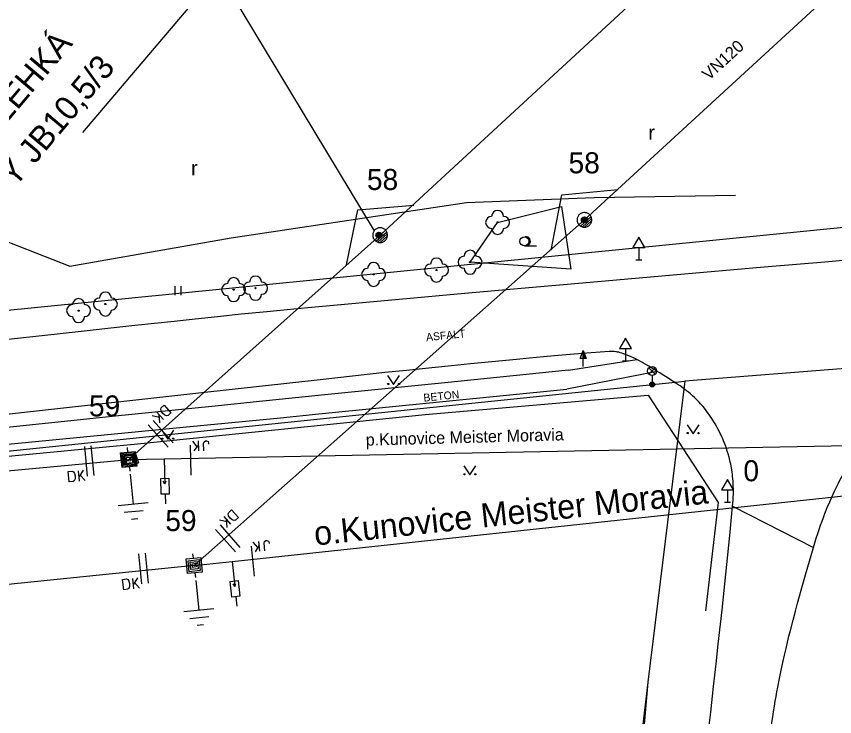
# Model space of a CAD drawing. Extents: x -540150 to -533593, y -1185082 to -1180066.
# Drawn here: x -536508.6 to -536440.4, y -1183065 to -1183006.7 of the extents above; entities that cross this region are included whole.
import ezdxf

# ---------------------------------------------------------------- set-up
doc = ezdxf.new("R2010")
doc.units = 0
for name, color, linetype in [('KN_HRAN_PARCEL', 7, 'Continuous'), ('KN_VKP_HRAN_', 7, 'Continuous'), ('popis demontáže', 7, 'Continuous'), ('Vrstva 1', 7, 'Continuous'), ('Vrstva 10', 7, 'Continuous'), ('Vrstva 11', 7, 'Continuous'), ('Vrstva 12', 7, 'Continuous'), ('Vrstva 13', 7, 'Continuous'), ('Vrstva 14', 7, 'Continuous'), ('Vrstva 15', 7, 'Continuous'), ('Vrstva 16', 7, 'Continuous'), ('Vrstva 18', 7, 'Continuous'), ('Vrstva 2', 7, 'Continuous'), ('Vrstva 21', 7, 'Continuous'), ('Vrstva 22', 7, 'Continuous'), ('Vrstva 23', 7, 'Continuous'), ('Vrstva 25', 7, 'Continuous'), ('Vrstva 3', 7, 'Continuous'), ('Vrstva 33', 7, 'Continuous'), ('Vrstva 34', 7, 'Continuous'), ('Vrstva 36', 7, 'Continuous'), ('Vrstva 4', 7, 'Continuous'), ('Vrstva 40', 7, 'Continuous'), ('Vrstva 52', 7, 'Continuous'), ('Vrstva 54', 7, 'Continuous'), ('Vrstva 59', 7, 'Continuous'), ('Vrstva 7', 7, 'Continuous')]:
    doc.layers.add(name, color=color, linetype=linetype)

# ---------------------------------------------------------------- blocks, each defined once
blk = doc.blocks.new('VN440')
at = {"layer": 'Vrstva 2'}
for points in [[(1.22, 0), (1.21, 0.13), (1.19, 0.25), (1.16, 0.38), (1.11, 0.5), (1.05, 0.61), (0.98, 0.72), (0.9, 0.82), (0.81, 0.91), (0.71, 0.99), (0.6, 1.06), (0.49, 1.12), (0.37, 1.16), (0.25, 1.2), (0.12, 1.22), (-0.01, 1.22), (-0.14, 1.22), (-0.26, 1.2), (-0.39, 1.16), (-0.51, 1.12), (-0.62, 1.06), (-0.73, 0.99), (-0.83, 0.91), (-0.92, 0.82), (-1, 0.72), (-1.07, 0.61), (-1.13, 0.5), (-1.18, 0.38), (-1.21, 0.25), (-1.23, 0.13), (-1.24, 0), (-1.23, -0.13), (-1.21, -0.26), (-1.18, -0.38), (-1.13, -0.5), (-1.07, -0.62), (-1, -0.73), (-0.92, -0.83), (-0.83, -0.92), (-0.73, -1), (-0.62, -1.07), (-0.51, -1.13), (-0.39, -1.17), (-0.26, -1.2), (-0.14, -1.23), (-0.01, -1.23), (0.12, -1.23), (0.25, -1.2), (0.37, -1.17), (0.49, -1.13), (0.6, -1.07), (0.71, -1), (0.81, -0.92), (0.9, -0.83), (0.98, -0.73), (1.05, -0.62), (1.11, -0.5), (1.16, -0.38), (1.19, -0.26), (1.21, -0.13), (1.22, 0)], [(-1.24, 0), (1.22, 0)], [(-1.18, -0.34), (1.1, -0.34)], [(-1.01, -0.63), (0.97, -0.63)], [(-0.74, -0.92), (0.68, -0.92)]]:
    blk.add_lwpolyline(points, dxfattribs=at)
blk = doc.blocks.new('VN850')
at = {"layer": 'Vrstva 15'}
for points in [[(-0.565, 1.426), (-0.565, -1.074)], [(-0.014, 1.426), (-0.014, -1.074)], [(-2.091, -0.542), (-1.776, -0.542)], [(-2.091, -1.409), (-2.091, -0.542)], [(-1.776, -0.542), (-1.657, -0.602)], [(-1.657, -0.602), (-1.588, -0.749)], [(-1.264, -0.542), (-1.264, -1.409)], [(-0.85, -0.542), (-1.264, -1.094)], [(-1.667, -1.35), (-1.776, -1.409)], [(-1.588, -1.202), (-1.667, -1.35)], [(-1.588, -0.749), (-1.549, -0.956)], [(-1.549, -0.956), (-1.588, -1.202)], [(-1.126, -0.917), (-0.772, -1.409)], [(-1.776, -1.409), (-2.091, -1.409)]]:
    blk.add_lwpolyline(points, dxfattribs=at)
blk = doc.blocks.new('VN840')
at = {"layer": 'Vrstva 15'}
for points in [[(-0.009, 1.414), (-0.009, -1.086)], [(-1.092, -0.594), (-1.092, -1.243)], [(-0.678, -0.594), (-0.678, -1.421)], [(-0.678, -1.106), (-0.265, -0.594)], [(-1.505, -1.243), (-1.505, -1.145)], [(-1.476, -1.352), (-1.505, -1.243)], [(-1.328, -1.421), (-1.476, -1.352)], [(-1.131, -1.352), (-1.269, -1.421)], [(-1.092, -1.243), (-1.131, -1.352)], [(-0.541, -0.938), (-0.196, -1.421)], [(-1.269, -1.421), (-1.328, -1.421)]]:
    blk.add_lwpolyline(points, dxfattribs=at)
blk = doc.blocks.new('VN860')
at = {"layer": 'Vrstva 15'}
for points in [[(-3.738, 0.001), (0.012, 2.82)], [(0.012, 2.82), (3.762, 0.001)]]:
    blk.add_lwpolyline(points, dxfattribs=at)
blk = doc.blocks.new('VN820')
at = {"layer": 'Vrstva 13'}
for points in [[(0.003, 0.002), (0.003, -2.105)], [(-0.322, -1.632), (0.338, -1.632)], [(-0.322, -2.951), (-0.322, -1.632)], [(0.003, -2.105), (-0.115, -1.859)], [(0.003, -2.105), (0.121, -1.859)], [(0.338, -1.632), (0.338, -2.951)], [(0.338, -2.951), (-0.322, -2.951)], [(0.003, -2.951), (0.003, -3.748)]]:
    blk.add_lwpolyline(points, dxfattribs=at)
blk = doc.blocks.new('VN810')
at = {"layer": 'Vrstva 14'}
for points in [[(0.004, -1.247), (0.004, -3.747)], [(1.254, -3.747), (-1.246, -3.747)], [(0.772, -4.367), (-0.803, -4.367)], [(0.004, -4.997), (-0.252, -4.997)], [(0.27, -4.997), (0.004, -4.997)]]:
    blk.add_lwpolyline(points, dxfattribs=at)
blk = doc.blocks.new('VN470')
at = {"layer": 'Vrstva 2'}
for points in [[(0, 1.22), (0, 1.97)], [(-1.23, 1.22), (1.23, 1.22)], [(-1.23, -1.23), (-1.23, 1.22)], [(-0.92, 0.9), (0.92, 0.9)], [(-0.92, -0.95), (-0.92, 0.9)], [(-0.61, 0.61), (0.61, 0.61)], [(-0.61, -0.62), (-0.61, 0.61)], [(-0.31, -0.27), (-0.31, 0.34)], [(-0.31, 0.34), (0.31, 0.34)], [(0.31, 0.34), (0.31, -0.27)], [(0.61, 0.61), (0.61, -0.62)], [(0.92, 0.9), (0.92, -0.95)], [(1.23, 1.22), (1.23, -1.23)], [(1.23, -1.23), (-1.23, -1.23)], [(0.92, -0.95), (-0.92, -0.95)], [(0.61, -0.62), (-0.61, -0.62)], [(0.31, -0.27), (-0.31, -0.27)], [(0, -1.23), (0, -1.98)]]:
    blk.add_lwpolyline(points, dxfattribs=at)

msp = doc.modelspace()

# ---------------------------------------------------------------- linework, layer by layer
at = {"layer": 'KN_HRAN_PARCEL'}
for p, q in [((-536420.27, -1183022.305), (-536523.7, -1183032.575)), ((-536401.06, -1183033.005), (-536452.92, -1183037.025)), ((-536549.916, -1183047.069), (-536452.92, -1183037.025)), ((-536452.92, -1183037.025), (-536456, -1183062.095)), ((-536456, -1183062.095), (-536459.39, -1183089.795))]:
    msp.add_line(p, q, dxfattribs=at)
at = {"layer": 'KN_VKP_HRAN_'}
msp.add_line((-536456, -1183062.095), (-536464.67, -1183156.935), dxfattribs=at)
at = {"layer": 'popis demontáže'}
msp.add_lwpolyline([(-536503.077, -1183016.334), (-536491.77, -1183003.019), (-536478.809, -1183024.516)], dxfattribs=at)
at = {"layer": 'Vrstva 1'}
for points in [[(-535333.019, -1181707.832), (-535332.528, -1181735.448), (-535362.49, -1181817.717), (-535394.17, -1181900.488), (-535426.424, -1181985.389), (-535455.768, -1182060.901), (-535484.739, -1182136.414), (-535558.599, -1182202.844), (-535640.844, -1182277.719), (-535712.992, -1182341.229), (-535787.765, -1182409.749), (-535866.419, -1182480.663), (-535946.042, -1182552.999), (-536025.292, -1182625.409), (-536105.737, -1182698.417), (-536184.987, -1182770.529), (-536271.131, -1182848.999), (-536335.755, -1182908.243), (-536401.721, -1182968.908), (-536461.289, -1183023.605), (-536493.807, -1183052.389)], [(-536499.259, -1183043.554), (-536478.31, -1183024.875), (-536408.53, -1182960.475), (-536346.218, -1182903.25), (-536276.596, -1182839.443), (-536191.423, -1182762.095), (-536111.799, -1182689.909), (-536032.399, -1182617.798), (-535952.252, -1182544.864), (-535872.16, -1182472.665)], [(-536551.039, -1183048.391), (-536499.259, -1183043.554)], [(-536493.807, -1183052.389), (-536560.174, -1183059.148)]]:
    msp.add_lwpolyline(points, dxfattribs=at)
at = {"layer": 'Vrstva 10'}
for p, q in [((-536441.274, -1183027.117), (-536446.321, -1183027.554)), ((-536438.391, -1183026.866), (-536441.274, -1183027.117)), ((-536446.321, -1183027.554), (-536453.891, -1183028.205)), ((-536461.46, -1183028.865), (-536466.876, -1183029.346)), ((-536470.937, -1183029.709), (-536477.029, -1183030.259)), ((-536466.876, -1183029.346), (-536470.937, -1183029.709)), ((-536477.029, -1183030.259), (-536483.12, -1183030.815)), ((-536498.745, -1183032.416), (-536504.472, -1183033.048)), ((-536472.36, -1183035.751), (-536473.73, -1183035.891)), ((-536483.31, -1183036.915), (-536493.16, -1183038.001)), ((-536493.16, -1183038.001), (-536507.935, -1183039.637)), ((-536507.935, -1183039.637), (-536515.322, -1183040.453)), ((-536499.893, -1183043.066), (-536498.771, -1183042.922)), ((-536499.749, -1183044.188), (-536499.893, -1183043.066)), ((-536499.669, -1183043.239), (-536498.944, -1183043.146)), ((-536499.576, -1183043.964), (-536499.669, -1183043.239)), ((-536498.944, -1183043.146), (-536498.851, -1183043.871)), ((-536498.771, -1183042.922), (-536498.627, -1183044.044)), ((-536498.627, -1183044.044), (-536499.749, -1183044.188)), ((-536498.851, -1183043.871), (-536499.576, -1183043.964)), ((-536449.599, -1183053.915), (-536449.431, -1183052.299)), ((-536450.772, -1183064.605), (-536450.527, -1183062.46))]:
    msp.add_line(p, q, dxfattribs=at)
for points in [[(-536453.891, -1183028.205), (-536457.676, -1183028.533), (-536461.46, -1183028.865)], [(-536483.12, -1183030.815), (-536484.326, -1183030.927), (-536485.494, -1183031.038), (-536487.756, -1183031.259), (-536489.876, -1183031.472), (-536491.863, -1183031.678)], [(-536491.863, -1183031.678), (-536493.726, -1183031.874), (-536495.472, -1183032.061), (-536498.745, -1183032.416)], [(-536504.472, -1183033.048), (-536508.767, -1183033.522), (-536511.989, -1183033.872), (-536514.406, -1183034.13)], [(-536454.801, -1183036.49), (-536455.01, -1183036.358), (-536455.22, -1183036.225), (-536455.43, -1183036.091), (-536455.612, -1183035.976), (-536455.931, -1183035.78), (-536456.173, -1183035.638), (-536456.357, -1183035.533), (-536456.497, -1183035.457), (-536456.71, -1183035.344), (-536456.93, -1183035.235), (-536457.21, -1183035.101), (-536457.456, -1183034.986), (-536457.673, -1183034.891), (-536457.863, -1183034.814), (-536458.031, -1183034.753), (-536458.179, -1183034.704), (-536458.308, -1183034.666), (-536458.422, -1183034.637), (-536458.522, -1183034.615), (-536458.609, -1183034.599), (-536458.686, -1183034.586), (-536458.821, -1183034.57), (-536458.923, -1183034.562), (-536458.999, -1183034.559), (-536459.115, -1183034.559), (-536459.23, -1183034.565), (-536460.734, -1183034.684), (-536462.145, -1183034.8), (-536463.468, -1183034.912)], [(-536463.468, -1183034.912), (-536464.708, -1183035.021), (-536465.871, -1183035.126), (-536466.962, -1183035.226), (-536469.006, -1183035.42), (-536470.795, -1183035.595), (-536472.36, -1183035.751)], [(-536473.73, -1183035.891), (-536476.126, -1183036.14), (-536477.923, -1183036.33), (-536480.617, -1183036.621), (-536483.31, -1183036.915)], [(-536449.074, -1183044.104), (-536449.104, -1183043.948), (-536449.136, -1183043.796), (-536449.17, -1183043.65), (-536449.24, -1183043.367), (-536449.313, -1183043.102), (-536449.388, -1183042.855), (-536449.464, -1183042.625), (-536449.54, -1183042.409), (-536449.616, -1183042.208), (-536449.691, -1183042.02), (-536449.765, -1183041.844), (-536449.837, -1183041.68), (-536449.908, -1183041.527), (-536449.977, -1183041.383), (-536450.043, -1183041.249), (-536450.174, -1183040.999), (-536450.294, -1183040.782), (-536450.404, -1183040.592), (-536450.504, -1183040.427), (-536450.594, -1183040.284), (-536450.675, -1183040.158), (-536450.822, -1183039.94), (-536450.936, -1183039.778), (-536451.024, -1183039.656), (-536451.16, -1183039.475), (-536451.3, -1183039.295), (-536451.41, -1183039.16), (-536451.517, -1183039.032), (-536451.622, -1183038.913), (-536451.725, -1183038.801), (-536451.825, -1183038.695), (-536451.922, -1183038.595), (-536452.017, -1183038.501), (-536452.11, -1183038.412), (-536452.291, -1183038.246), (-536452.463, -1183038.096), (-536452.625, -1183037.961), (-536452.779, -1183037.838), (-536452.925, -1183037.727), (-536453.062, -1183037.625), (-536453.322, -1183037.44), (-536453.552, -1183037.283), (-536453.755, -1183037.149), (-536454.114, -1183036.918), (-536454.387, -1183036.747), (-536454.801, -1183036.49)], [(-536449.431, -1183052.299), (-536449.183, -1183049.877), (-536448.94, -1183047.455), (-536448.916, -1183047.191), (-536448.899, -1183046.936), (-536448.887, -1183046.688), (-536448.88, -1183046.449), (-536448.878, -1183046.216), (-536448.88, -1183045.991), (-536448.886, -1183045.774), (-536448.896, -1183045.563), (-536448.91, -1183045.359), (-536448.926, -1183045.161), (-536448.945, -1183044.97), (-536448.967, -1183044.785), (-536448.991, -1183044.607), (-536449.016, -1183044.434), (-536449.044, -1183044.266), (-536449.074, -1183044.104)], [(-536441.852, -1183049.733), (-536441.733, -1183049.376), (-536441.614, -1183049.031), (-536441.496, -1183048.7), (-536441.378, -1183048.38), (-536441.261, -1183048.071), (-536441.144, -1183047.774), (-536441.028, -1183047.487), (-536440.913, -1183047.211), (-536440.798, -1183046.945), (-536440.685, -1183046.689), (-536440.572, -1183046.441), (-536440.46, -1183046.203), (-536440.35, -1183045.973), (-536440.241, -1183045.752), (-536440.132, -1183045.539), (-536440.026, -1183045.333), (-536439.92, -1183045.135), (-536439.816, -1183044.944), (-536439.713, -1183044.76), (-536439.509, -1183044.405), (-536439.311, -1183044.076), (-536439.119, -1183043.771)], [(-536442.09, -1183050.487), (-536441.971, -1183050.103), (-536441.852, -1183049.733)], [(-536444.624, -1183059.857), (-536444.494, -1183059.294), (-536444.369, -1183058.767), (-536444.248, -1183058.273), (-536444.134, -1183057.81), (-536443.912, -1183056.944), (-536443.713, -1183056.186), (-536443.535, -1183055.524), (-536443.376, -1183054.944), (-536443.093, -1183053.93), (-536442.876, -1183053.169), (-536442.546, -1183052.028), (-536442.21, -1183050.885), (-536442.09, -1183050.487)], [(-536450.527, -1183062.46), (-536450.317, -1183060.584), (-536450.136, -1183058.942), (-536449.826, -1183056.069), (-536449.599, -1183053.915)], [(-536445.181, -1183062.518), (-536445.038, -1183061.785), (-536444.896, -1183061.099), (-536444.758, -1183060.458), (-536444.624, -1183059.857)], [(-536446.471, -1183071.943), (-536446.139, -1183069.184), (-536445.8, -1183066.425), (-536445.736, -1183065.931), (-536445.671, -1183065.453), (-536445.603, -1183064.991), (-536445.534, -1183064.544), (-536445.465, -1183064.111), (-536445.394, -1183063.693), (-536445.323, -1183063.288), (-536445.252, -1183062.897), (-536445.181, -1183062.518)], [(-536451.763, -1183072.826), (-536451.565, -1183071.241), (-536451.383, -1183069.755), (-536451.214, -1183068.362), (-536451.059, -1183067.055), (-536450.772, -1183064.605)]]:
    msp.add_lwpolyline(points, dxfattribs=at)
at = {"layer": 'Vrstva 11'}
for p, q in [((-536462.63, -1183036.125), (-536456.93, -1183035.235)), ((-536462.63, -1183036.125), (-536472.91, -1183037.165)), ((-536455.22, -1183036.225), (-536462.76, -1183037.705)), ((-536472.91, -1183037.165), (-536483.19, -1183038.205)), ((-536473.095, -1183038.735), (-536462.76, -1183037.705)), ((-536483.43, -1183039.765), (-536473.095, -1183038.735)), ((-536492.346, -1183039.139), (-536499.822, -1183039.91)), ((-536499.822, -1183039.91), (-536511.036, -1183041.074)), ((-536496.179, -1183041.017), (-536489.804, -1183040.395)), ((-536517.432, -1183043.065), (-536500.43, -1183041.428)), ((-536500.43, -1183041.428), (-536496.179, -1183041.017)), ((-536448.94, -1183047.455), (-536442.21, -1183050.885))]:
    msp.add_line(p, q, dxfattribs=at)
for points in [[(-536483.19, -1183038.205), (-536488.073, -1183038.701), (-536492.346, -1183039.139)], [(-536489.804, -1183040.395), (-536486.617, -1183040.081), (-536483.43, -1183039.765)]]:
    msp.add_lwpolyline(points, dxfattribs=at)
at = {"layer": 'Vrstva 21'}
msp.add_lwpolyline([(-536468.52, -1183023.815), (-536463.19, -1183022.495), (-536462.41, -1183027.715), (-536470.82, -1183027.135), (-536468.52, -1183023.815)], dxfattribs=at)
at = {"layer": 'Vrstva 22'}
for centre in [(-536468.52, -1183023.815), (-536470.82, -1183027.135), (-536473.61, -1183027.785), (-536478.85, -1183028.145), (-536490.52, -1183029.415), (-536488.69, -1183029.295), (-536501.2, -1183030.615), (-536503.43, -1183031.165)]:
    msp.add_circle(centre, 0.05, dxfattribs=at)
for centre, start, end in [((-536468.52, -1183023.315), 0, 180), ((-536469.02, -1183023.815), 90, 270), ((-536468.02, -1183023.815), 270, 90), ((-536468.52, -1183024.315), 180, 0), ((-536470.82, -1183026.635), 0, 180), ((-536478.85, -1183027.645), 0, 180), ((-536473.61, -1183027.285), 0, 180), ((-536471.32, -1183027.135), 90, 270), ((-536470.32, -1183027.135), 270, 90), ((-536479.35, -1183028.145), 90, 270), ((-536478.35, -1183028.145), 270, 90), ((-536474.11, -1183027.785), 90, 270), ((-536473.11, -1183027.785), 270, 90), ((-536470.82, -1183027.635), 180, 0), ((-536490.52, -1183028.915), 0, 180), ((-536488.69, -1183028.795), 0, 180), ((-536473.61, -1183028.285), 180, 0), ((-536491.02, -1183029.415), 90, 270), ((-536490.02, -1183029.415), 270, 90), ((-536489.19, -1183029.295), 90, 270), ((-536488.19, -1183029.295), 270, 90), ((-536478.85, -1183028.645), 180, 0), ((-536501.2, -1183030.115), 0, 180), ((-536490.52, -1183029.915), 180, 0), ((-536488.69, -1183029.795), 180, 0), ((-536503.43, -1183030.665), 0, 180), ((-536501.7, -1183030.615), 90, 270), ((-536500.7, -1183030.615), 270, 90), ((-536503.93, -1183031.165), 90, 270), ((-536502.93, -1183031.165), 270, 90), ((-536501.2, -1183031.115), 180, 0), ((-536503.43, -1183031.665), 180, 0)]:
    msp.add_arc(centre, 0.5, start, end, dxfattribs=at)
at = {"layer": 'Vrstva 23'}
msp.add_lwpolyline([(-536520.38, -1183017.135), (-536515.51, -1183023.015), (-536504.15, -1183027.465), (-536490.71, -1183025.095), (-536471.12, -1183022.165), (-536460.47, -1183021.735), (-536448.71, -1183021.545)], dxfattribs=at)
at = {"layer": 'Vrstva 25'}
for p, q in [((-536461.642, -1183035.163), (-536461.39, -1183034.489)), ((-536461.39, -1183035.163), (-536461.642, -1183035.163)), ((-536461.39, -1183035.815), (-536461.39, -1183035.165))]:
    msp.add_line(p, q, dxfattribs=at)
for points in [[(-536461.14, -1183035.165), (-536461.39, -1183035.165), (-536461.39, -1183034.489), (-536461.39, -1183034.489)], [(-536461.197, -1183035.125), (-536461.35, -1183035.125), (-536461.35, -1183034.712)], [(-536461.255, -1183035.085), (-536461.31, -1183035.085), (-536461.31, -1183034.936)]]:
    msp.add_lwpolyline(points, close=True, dxfattribs=at)
for centre, radius in [((-536461.29, -1183023.605), 0.25), ((-536461.29, -1183023.605), 0.2), ((-536461.29, -1183023.605), 0.15), ((-536461.29, -1183023.605), 0.1), ((-536461.29, -1183023.605), 0.05), ((-536478.41, -1183024.885), 0.25), ((-536478.41, -1183024.885), 0.2), ((-536478.41, -1183024.885), 0.15), ((-536478.41, -1183024.885), 0.1), ((-536478.41, -1183024.885), 0.05)]:
    msp.add_circle(centre, radius, dxfattribs=at)
at = {"layer": 'Vrstva 33'}
for p, q in [((-536455.915, -1183036.455), (-536455.385, -1183035.925)), ((-536455.915, -1183035.925), (-536455.385, -1183036.455)), ((-536455.65, -1183036.565), (-536455.65, -1183037.315))]:
    msp.add_line(p, q, dxfattribs=at)
for centre, radius in [((-536455.65, -1183036.19), 0.375), ((-536455.65, -1183037.315), 0.2), ((-536455.65, -1183037.315), 0.145), ((-536455.65, -1183037.315), 0.0876)]:
    msp.add_circle(centre, radius, dxfattribs=at)
at = {"layer": 'Vrstva 34'}
for p, q in [((-536456.76, -1183025.917), (-536456.76, -1183026.935)), ((-536457.01, -1183026.935), (-536456.51, -1183026.935)), ((-536457.88, -1183034.317), (-536457.88, -1183035.335)), ((-536458.13, -1183035.335), (-536457.63, -1183035.335)), ((-536449.36, -1183046.097), (-536449.36, -1183047.115)), ((-536449.61, -1183047.115), (-536449.11, -1183047.115))]:
    msp.add_line(p, q, dxfattribs=at)
for points in [[(-536457.26, -1183025.917), (-536456.26, -1183025.917), (-536456.76, -1183025.051)], [(-536458.38, -1183034.317), (-536457.38, -1183034.317), (-536457.88, -1183033.451)], [(-536449.86, -1183046.097), (-536448.86, -1183046.097), (-536449.36, -1183045.231)]]:
    msp.add_lwpolyline(points, close=True, dxfattribs=at)
at = {"layer": 'Vrstva 36'}
for p, q in [((-536466.285, -1183025.776), (-536465.285, -1183025.776)), ((-536495.398, -1183029.871), (-536495.398, -1183029.121)), ((-536494.898, -1183029.871), (-536494.898, -1183029.121))]:
    msp.add_line(p, q, dxfattribs=at)
for points in [[(-536477.685, -1183036.573), (-536477.185, -1183037.323), (-536476.685, -1183036.573)], [(-536452.734, -1183040.661), (-536452.234, -1183041.411), (-536451.734, -1183040.661)], [(-536496.504, -1183041.124), (-536496.004, -1183041.874), (-536495.504, -1183041.124)], [(-536471.334, -1183044.092), (-536470.834, -1183044.842), (-536470.334, -1183044.092)]]:
    msp.add_lwpolyline(points, dxfattribs=at)
for centre, radius in [((-536466.285, -1183025.4), 0.375), ((-536477.635, -1183037.272), 0.05), ((-536476.735, -1183037.272), 0.05), ((-536452.685, -1183041.361), 0.05), ((-536451.785, -1183041.361), 0.05), ((-536496.454, -1183041.824), 0.05), ((-536495.555, -1183041.824), 0.05), ((-536471.284, -1183044.792), 0.05), ((-536470.385, -1183044.792), 0.05)]:
    msp.add_circle(centre, radius, dxfattribs=at)
msp.add_arc((-536466.16, -1183025.4), 0.375, 260.40593, 99.59407, dxfattribs=at)
at = {"layer": 'Vrstva 4'}
msp.add_lwpolyline([(-536499.259, -1183043.554), (-536496.312, -1183043.495), (-536432.17, -1183042.245)], dxfattribs=at)
at = {"layer": 'Vrstva 52'}
msp.add_lwpolyline([(-536493.807, -1183052.389), (-536490.644, -1183052.05), (-536434.5, -1183046.025)], dxfattribs=at)
at = {"layer": 'Vrstva 7'}
for p, q in [((-536522.12, -1183044.495), (-536498.52, -1183042.245)), ((-536499.329, -1183044.14), (-536498.449, -1183043.85))]:
    msp.add_line(p, q, dxfattribs=at)
for points in [[(-536498.52, -1183042.245), (-536474.56, -1183039.825), (-536455.97, -1183038.205), (-536450.15, -1183047.135), (-536451.2, -1183056.165)], [(-536499.329, -1183044.14), (-536499.61, -1183043.285), (-536498.73, -1183042.995), (-536498.449, -1183043.85)]]:
    msp.add_lwpolyline(points, dxfattribs=at)

# ---------------------------------------------------------------- block references
at = {"layer": 'Vrstva 13'}
for name, p, xscale, yscale, rotation in [('VN440', (-536461.289, -1183023.605), 0.5, 0.5, 41.44218061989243), ('VN440', (-536478.311, -1183024.875), 0.5, 0.5, 41.722772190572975), ('VN440', (-536478.311, -1183024.875), 0.5, 0.5, 41.722772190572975), ('VN470', (-536499.26, -1183043.555), 0.49999999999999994, 0.5000000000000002, 5.629222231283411), ('VN470', (-536493.807, -1183052.39), 0.5000000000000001, 0.5, 5.814858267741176)]:
    msp.add_blockref(name, p, dxfattribs=dict(at, xscale=xscale, yscale=yscale, rotation=rotation))
at = {"layer": 'Vrstva 15'}
for p, rotation in [((-536499.259, -1183043.555), 5.629222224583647), ((-536493.807, -1183052.39), 5.814858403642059)]:
    msp.add_blockref('VN810', p, dxfattribs=dict(at, rotation=rotation))
at = {"layer": 'Vrstva 16'}
for p, rotation in [((-536496.312, -1183043.495), 1.5765195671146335), ((-536490.644, -1183052.05), 5.958369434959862)]:
    msp.add_blockref('VN820', p, dxfattribs=dict(at, rotation=rotation))
at = {"layer": 'Vrstva 18'}
for name, p, rotation in [('VN860', (-536461.289, -1183023.604), 42.35320559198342), ('VN860', (-536478.311, -1183024.875), 41.721525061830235), ('VN850', (-536496.937, -1183041.484), -138.27847493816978), ('VN840', (-536494.089, -1183043.452), -178.88356102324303), ('VN850', (-536502.26, -1183043.834), 5.337066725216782), ('VN850', (-536491.327, -1183050.193), -138.5581694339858), ('VN840', (-536488.933, -1183051.866), -173.87483891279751), ('VN850', (-536497.737, -1183052.789), 5.815036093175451)]:
    msp.add_blockref(name, p, dxfattribs=dict(at, rotation=rotation))

# ---------------------------------------------------------------- texts
at = {"layer": 'popis demontáže'}
for s, p in [('- 1x KONZOLA ROVINNÁ LEHKÁ', (-536529.893, -1183039.873)), ('- 1x SLOUP BETONOVÝ JB10,5/3', (-536526.833, -1183042.45))]:
    msp.add_text(s, height=2, rotation=49.88813, dxfattribs=at).set_placement(p)
at = {"layer": 'Vrstva 12'}
msp.add_text('0', height=1.75, dxfattribs=at).set_placement((-536448.044, -1183045.374))
at = {"layer": 'Vrstva 14'}
for s, p in [('58', (-536462.611, -1183019.733)), ('58', (-536479.41, -1183021.12)), ('59', (-536502.567, -1183039.975)), ('59', (-536496.208, -1183049.519))]:
    msp.add_text(s, height=1.75, dxfattribs=at).set_placement(p)
at = {"layer": 'Vrstva 3'}
msp.add_text('VN120', height=1, rotation=42.559, dxfattribs=at).set_placement((-536450.923, -1183012.044))
at = {"layer": 'Vrstva 36'}
for p in [(-536455.958, -1183016.934), (-536494.055, -1183019.89)]:
    msp.add_text('r', height=1.2, dxfattribs=at).set_placement(p)
at = {"layer": 'Vrstva 40'}
for s, rotation, p in [('ASFALT', 5.84231, (-536474.454, -1183033.712)), ('BETON', 5.69138, (-536474.67, -1183038.749))]:
    msp.add_text(s, height=0.65, rotation=rotation, dxfattribs=at).set_placement(p)
at = {"layer": 'Vrstva 54'}
msp.add_text('o.Kunovice Meister Moravia', height=2, rotation=6.125, dxfattribs=at).set_placement((-536483.712, -1183050.728))
at = {"layer": 'Vrstva 59'}
msp.add_text('p.Kunovice Meister Moravia', height=1, rotation=1.577, dxfattribs=at).set_placement((-536479.497, -1183042.418))

doc.saveas('drawing.dxf')
